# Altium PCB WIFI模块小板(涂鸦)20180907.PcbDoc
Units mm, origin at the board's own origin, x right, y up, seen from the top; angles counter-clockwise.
Board outline 152.4 x 101.6 mm, 2 copper layers (Top Layer, Bottom Layer); 1 components, 4 nets, 24 pads, 3 vias.
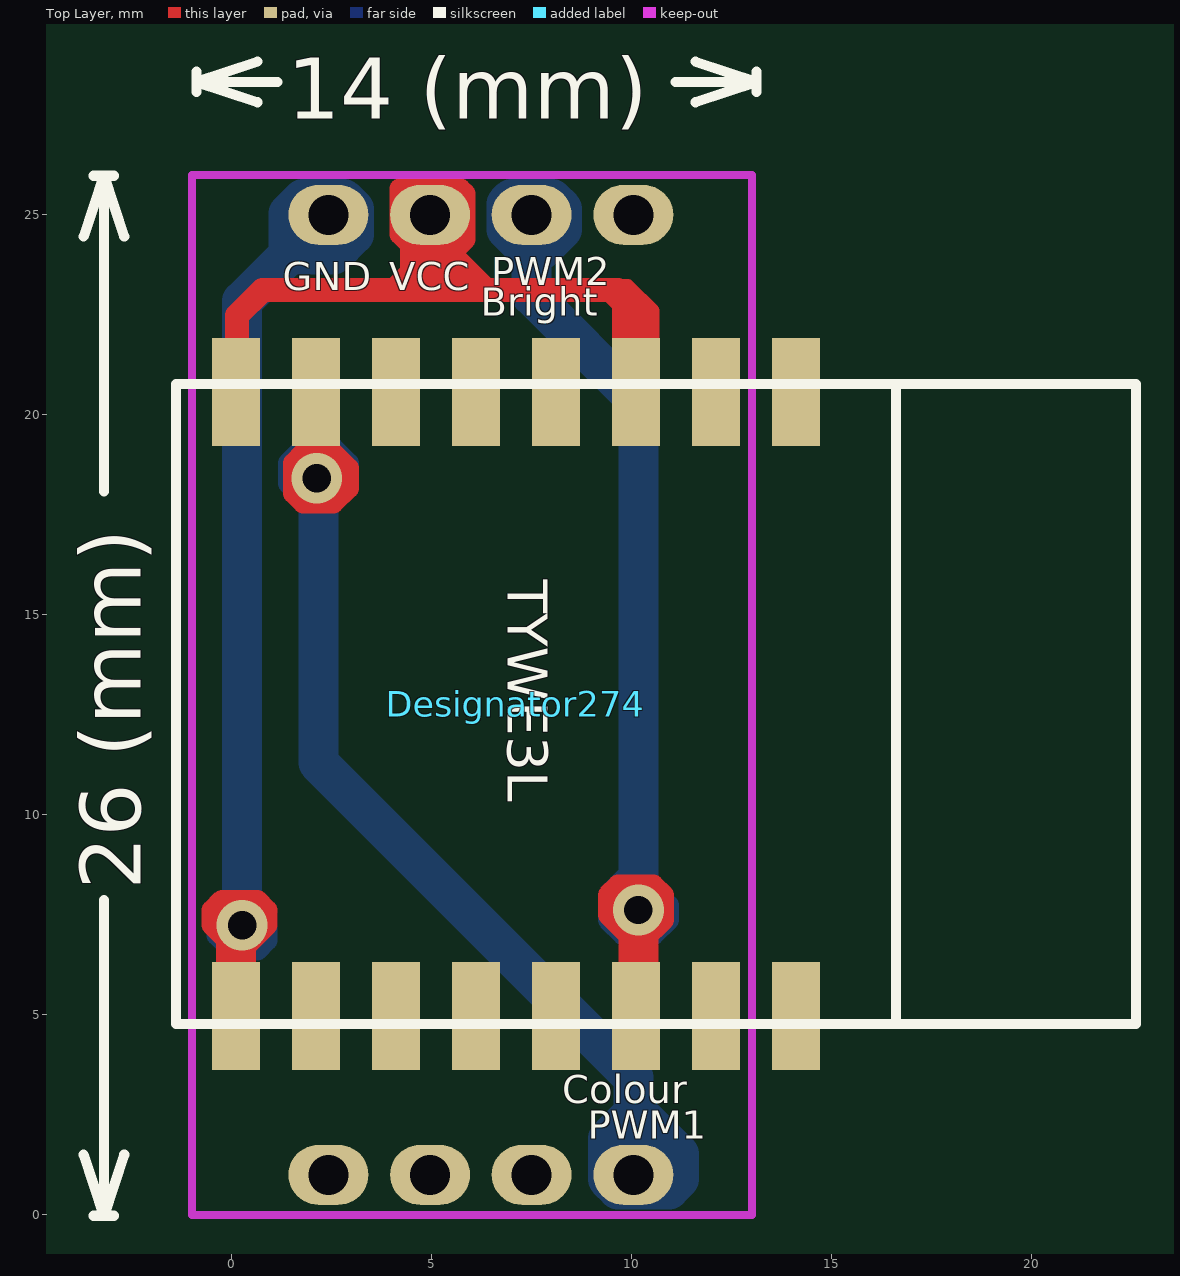
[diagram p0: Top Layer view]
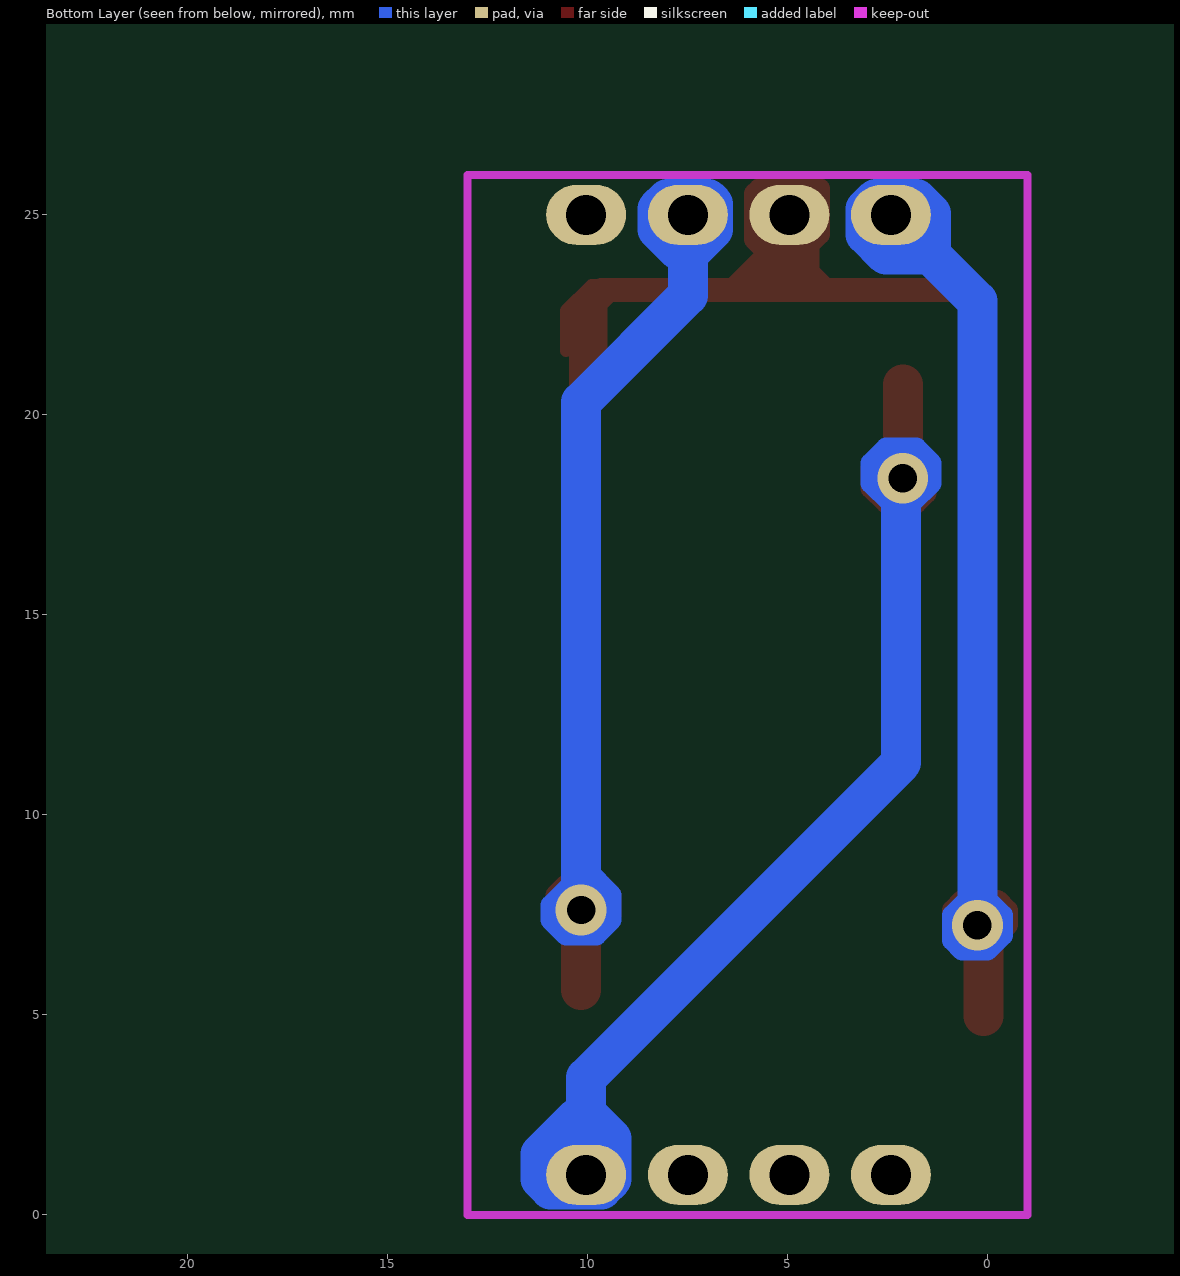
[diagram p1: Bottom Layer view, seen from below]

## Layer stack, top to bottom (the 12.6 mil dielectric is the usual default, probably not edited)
Top Solder: solder mask 0.0102, Solder Resist, Dk 3.5
Top Layer: signal copper 0.0356
Dielectric1: dielectric 0.32, FR-4, Dk 4.8
Bottom Layer: signal copper 0.0356
Bottom Solder: solder mask 0.0102, Solder Resist, Dk 3.5

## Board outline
-71.374,-52.467 81.026,-52.467 81.026,49.133 -71.374,49.133

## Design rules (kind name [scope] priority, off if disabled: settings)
Clearance [All] p1: gap=0.254 ignorepadtopadclearanceinfootprint=FALSE except(0: Arc-Hole Track-Hole SMDPad-Hole THPad-Hole Via-Hole Fill-Hole Poly-Hole Region-Hole Text-Hole)
PolygonConnect [All] p1: connectstyle=Direct reliefconductorwidth=0.254 reliefentries=4 polygonreliefangle="90 Angle" airgapwidth=0.254
RoutingVias [All] p1: holewidth=0.711 width=1.27 viastyle="Through Hole" minholewidth=0.711 minwidth=1.27 maxholewidth=0.711 maxwidth=1.27
SilkToSolderMaskClearance SilkscreenOverComponentPads [IsPad] p1: minsilkscreentomaskgap=0.254 clearancetoexposedcopper=TRUE
SolderMaskExpansion [All] p1: expansion=0.102
Width [All] p1: maxlimit=1 minlimit=0.254 preferedwidth=0.6
29 further rules are at their usual default settings.

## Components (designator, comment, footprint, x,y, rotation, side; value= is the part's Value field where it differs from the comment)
Designator274 "Comment" TYWE3L-P -1.403,12.774 r270 top

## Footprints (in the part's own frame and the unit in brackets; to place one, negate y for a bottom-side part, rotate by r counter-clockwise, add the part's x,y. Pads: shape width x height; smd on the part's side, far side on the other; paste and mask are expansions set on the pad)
TYWE3L-P [mm]
  rect 2.7x1.2 smd: 1(-7.8,15.5) 2(-7.8,13.5) 3(-7.8,11.5) 4EN(-7.8,9.5) 5(-7.8,7.5) 6(-7.8,5.5) 7PWM1(-7.8,3.5) 8VCC(-7.8,1.5) 9GND(7.8,1.5) 10(7.8,3.5) 11(7.8,5.5) 12(7.8,7.5) 13(7.8,9.5) 14PWM2(7.8,11.5) 15(7.8,13.5) 16(7.8,15.5)
  silkscreen extent -8,0 8,24

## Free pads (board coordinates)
  oval 2x1.5 hole 1: 2(2.413,1) 2(2.413,25) 2(4.953,1) 2(4.953,25) 2(7.493,1) 2(7.493,25) 2(10.033,1) 2(10.033,25)

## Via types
v1: diameter 1.27, hole 0.711, Top Layer to Bottom Layer, tented both sides, 3 vias

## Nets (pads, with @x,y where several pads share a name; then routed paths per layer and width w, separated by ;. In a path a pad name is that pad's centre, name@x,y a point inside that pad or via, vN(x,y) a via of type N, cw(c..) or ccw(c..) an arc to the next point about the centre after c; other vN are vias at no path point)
3: Designator274.8VCC pad.2@4.953,25 | length 7.8
  Top Layer w0.6: Designator274.8VCC@0.127,21.127 0.127,22.479 0.762,23.114 4.064,23.114 4.953,24.003 pad.2@4.953,25
GND1: Designator274.9GND pad.2@2.413,25 | length 21
  Top Layer w1: Designator274.9GND 0.097,7.082 v1(0.254,7.239)
  Bottom Layer w1: v1(0.254,7.239) 0.254,22.841 pad.2@2.413,25
NewNet14: Designator274.14PWM2 pad.2@7.493,25 | length 20.4
  Top Layer w1: Designator274.14PWM2@10.16,5.621 v1(10.16,7.62)
  Bottom Layer w1: pad.2@7.493,25 7.493,22.987 10.16,20.32 v1@10.16,7.747
NewNet15: Designator274.7PWM1 pad.2@10.033,1 | length 22.8
  Top Layer w1: v1(2.119,18.415) Designator274.7PWM1@2.119,20.754
  Bottom Layer w1: v1@2.159,18.161 2.159,11.303 10.033,3.429 pad.2@10.033,1
pads on no net: Designator274.1 Designator274.2 Designator274.3 Designator274.4EN Designator274.5 Designator274.6 Designator274.10 Designator274.11 Designator274.12 Designator274.13 Designator274.15 Designator274.16
copper on no net: | length 66.5
  Top Layer w0.3: 9.652,21.463 9.652,22.733 9.271,23.114 9.398,23.241 9.906,23.241 10.541,22.606 10.541,21.59 ; 9.779,21.336 9.779,22.733 9.906,22.86
  Top Layer w0.5: -0.127,6.731 -0.127,6.858 -0.508,7.239 -0.508,7.62 -0.254,7.874 0.635,7.874 0.889,7.62 0.889,7.239 0.381,6.731 ; 1.778,19.05 1.524,18.796 1.524,18.034 1.778,17.78 2.54,17.78 2.921,18.161 2.921,18.669 2.54,19.05 ; 4.445,24.257 4.445,23.622 4.508,23.558 ; 10.033,6.858 9.398,7.493 9.398,8.001 9.652,8.255 10.541,8.255 10.795,8.001 10.795,7.366 10.287,6.858 ; 4.191,24.511 4.699,24.003 5.461,24.003 5.842,24.384 5.842,25.527 5.715,25.654 4.191,25.654 4.191,24.511
  Top Layer w0.6: 4.064,23.114 6.35,23.114 ; 4.699,23.495 5.969,23.495 6.096,23.368 ; 5.207,25.146 5.207,24.257 6.35,23.114 ; 10.097,20.574 10.16,20.637 10.16,22.606 9.652,23.114 6.35,23.114
  Bottom Layer w0.5: 0.254,8.382 0.254,8.128 ; 1.905,17.78 1.397,18.288 1.397,18.796 1.524,18.923 1.778,19.177 2.54,19.177 2.921,18.796 2.921,18.288 2.413,17.78 ; 10.033,8.382 10.287,8.382 10.922,7.747 10.922,7.366 10.541,6.985 9.779,6.985 9.398,7.366 9.398,8.001 10.033,8.636 ; 0.254,8.128 -0.381,7.493 -0.381,6.985 0,6.604 0.635,6.604 0.889,6.858 0.889,7.493 0.254,8.128
  Bottom Layer w1: 7.493,23.876 7.493,24.003 6.858,24.638 6.858,25.273 6.985,25.4 8.001,25.4 8.255,25.146 8.255,24.638 7.747,24.13 ; 10.033,2.54 9.398,1.905 9.398,0.889 9.652,0.635 10.922,0.635 11.176,0.889 11.176,1.524 10.287,2.413 ; 1.416,24.003 2.54,24.003 3.048,24.511 3.048,25.146 2.794,25.4 1.778,25.4 1.416,25.038 1.416,24.003

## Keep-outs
Keep-Out Layer:
  lines w0.2: -1,0 -1,26 13,26 13,0 -1,0

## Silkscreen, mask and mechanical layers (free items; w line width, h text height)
Top Overlay:
  lines w0.254: -3.708,1.502 -3.2,-0.022 ; -3.708,24.454 -3.2,25.978 ; -3.454,-0.022 -2.946,-0.022 ; -3.454,25.978 -2.946,25.978 ; -3.2,7.874 -3.2,-0.022 ; -3.2,18.082 -3.2,25.978 ; -2.692,1.502 -3.2,-0.022 ; -2.692,24.454 -3.2,25.978 ; -0.889,28.067 -0.889,28.575 ; 0.635,27.813 -0.889,28.321 ; 0.635,28.829 -0.889,28.321 ; 1.134,28.321 -0.889,28.321 ; 11.088,28.321 13.111,28.321 ; 11.587,27.813 13.111,28.321 ; 11.587,28.829 13.111,28.321 ; 13.111,28.067 13.111,28.575
  text "14 (mm)" at 1.388,27.407 h1.52
  text "PWM2" at 6.477,23.241 h0.7
  text "GND" at 1.27,23.114 h0.7
  text "VCC" at 3.937,23.114 h0.7
  text "Bright" at 6.223,22.479 h0.7
  text "26 (mm)" at -2.286,8.128 h1.52 r90
  text "Colour" at 8.255,2.794 h0.7
  text "PWM1" at 8.89,1.905 h0.7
